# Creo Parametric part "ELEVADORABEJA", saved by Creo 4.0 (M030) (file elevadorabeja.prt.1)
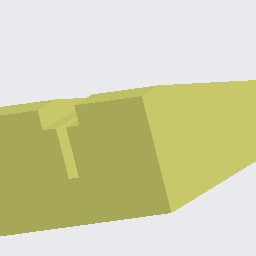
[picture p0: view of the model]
Units: millimeter Newton Second (mmNs); MM, TONNE, SECS

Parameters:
  MODELED_BY = "aj"

Created from: MMNS_PART_SOLID.PRT

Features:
  1. datum plane "RIGHT"
  2. datum plane "TOP"
  3. datum plane "FRONT"
  4. coordinate system
  5. extrusion "Extrude 1"
  6. extruded cut "Extrude 2"
  7. extruded cut "Extrude 3"
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
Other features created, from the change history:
  extruded cut "Extrude 4"

Surfaces: 14 plane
